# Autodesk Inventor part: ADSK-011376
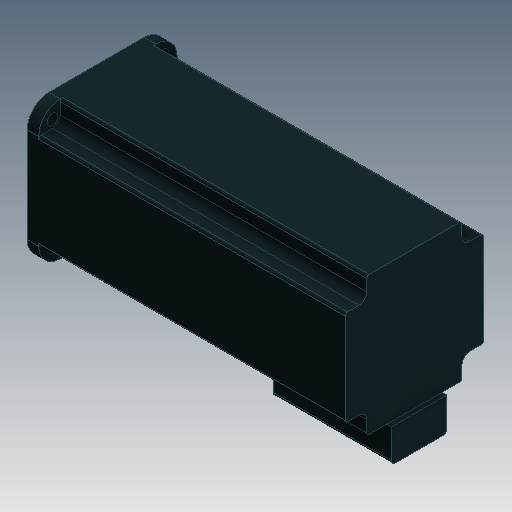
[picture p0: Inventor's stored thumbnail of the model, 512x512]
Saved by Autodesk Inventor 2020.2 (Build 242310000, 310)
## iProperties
Created: 1999-12
Part Number: ADSK-011376
Document SubType Name: Modeling
Designer: tgregory
Material: Pearson HRS
Density: 7.83 g/cm^3
Appearance: Servo Black
Mass: 25907.1 g
Surface Area: 1519.42 cm^2
Volume: 3308.69 cm^3
Control State: 0
Master: False
Checked Out: False
Shininess: 25.0
Length Units: 11272
Angle Units: 11279
Time Units: 11290
Mass Units: 11286
Length Display Precision: 3
Angle Display Precision: 2
Compacted: True
Dimensions: 5,6x4,5x10,7 in
Mass: 57,115 lb
VLT_Material: Pearson HRS
Density: 7.83
Volumn: 3540.041649508755
Area: 1483.7736859788888
PropertySet Name: Model Information
Author: tgregory
Revision Number: -
Title: ADSK-011376
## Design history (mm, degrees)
node "Extrusion1" dims "d2" = 115, "d3" = 0
node "Extrusion2" dims "d9" = 27.5, "d10" = 0
node "Hole1" dims "d12" = 9, "d13" = 9.525, "d14" = 6.35, "d15" = 60 deg, "d16" = 10, "d17" = 118 deg
node "Fillet1" dims "d18" = 18
node "Fillet2" dims "d19" = 3.175
workplane "Work Plane1"
workplane "Work Plane3"
workplane "Work Plane4"
workaxis "Work Axis3"
node "Extrusion3" dims "d26" = 254.5, "d27" = 0
node "Circular Pattern1" dims "d29" = 40, "d31" = 90 deg
node "Extrusion4" dims "d33" = 3, "d34" = 0
node "Solide1"
node "Corps solides"
node "Corps surfaciques"
sketch "Sketch1"
  geometry: L1 (0, 0)-(264, 0); L2 (264, 0)-(264, 115); L3 (264, 115)-(0, 115); L4 (0, 115)-(0, 0); 1 further point
  constraints: 8 end point, 2 parallel, 1 coincident, 1 horizontal, 1 perpendicular
  dimensions: "d0" = 115 distance between parallel lines of L3 L1; "d1" = 264 distance between parallel lines of L2 L4
sketch "Sketch2"
  geometry: L1 (264, 0)-(264, -115) reference; L2 (0, 0)-(0, -115) reference; L3 (264, -57.5)-(170, -57.5); L4 (170, -57.5)-(170, -34.5); L5 (170, -57.5)-(170, -80.5); L6 (268, -41.589)-(268, -80.5); L7 (170, -80.5)-(268, -80.5); L8 (268, -34.5)-(268, -80.5); L9 (268, -34.5)-(170, -34.5); L10 (170, -34.5)-(170, -80.5)
  constraints: 16 end point, 6 perpendicular, 1 collinear, 1 midpoint
  dimensions: "d4" = 94.00032 distance from line of L1 L3.end; "d5" = 22.9997 distance from line of L3 L4.end; "d6" = 22.9997 distance from line of L5.end L3 (= d5); "d22" = 98 distance between parallel lines of L6 L5
sketch "Sketch4"
  geometry: L1 (-57.5, 57.5)-(-115, 0); L2 (-57.5, 57.5)-(-115, 115); L3 (-57.5, 57.5)-(0, 115); L4 (-57.5, 57.5)-(0, 0); A1 r 65 centre (-57.5, 57.5) between (-103.462, 103.462) and (-11.538, 103.462); 2 further points
  constraints: 8 end point, 4 point on circle, 4 point on line, 3 perpendicular, 1 centre point
  dimensions: "d11" = 130 diameter of A1
sketch "Sketch5"
  geometry: L1 (-16.5, 115)-(62.5, 115) reference; L2 (-16.5, 97)-(-16.5, 113); L3 (-16.5, 97)-(-32.5, 97); L4 (-34.5, 18)-(-34.5, 97) reference; C1 r 4.5 at (-22.962, 103.462) reference; A1 r 18 centre (-16.5, 97) between (-16.5, 115) and (-34.5, 97) reference; A2 r 6.462 centre (-22.962, 103.462) between (-22.962, 97) and (-16.5, 103.462); A3 r 2 centre (-14.5, 113) between (-14.5, 115) and (-16.5, 113); A4 r 2 centre (-32.5, 95) between (-32.5, 97) and (-34.5, 95); 3 further points
  constraints: 6 point on circle, 5 tangent, 4 end point, 4 point on line, 3 centre point, 2 perpendicular, 1 coincident, 1 equal radius
  dimensions: "d28" = 4 diameter of A3
sketch "Sketch6"
  geometry: C1 r 47.5 at (-57.5, 39.5); 1 further point
  constraints: 1 centre point, 1 coincident
  dimensions: "d32" = 95 diameter of C1
other parameters: "d20" = -41.656, "d23" = -57.5, "d24" = -57.5
